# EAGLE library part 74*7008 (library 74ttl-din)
NOR/NAND/INVERTER
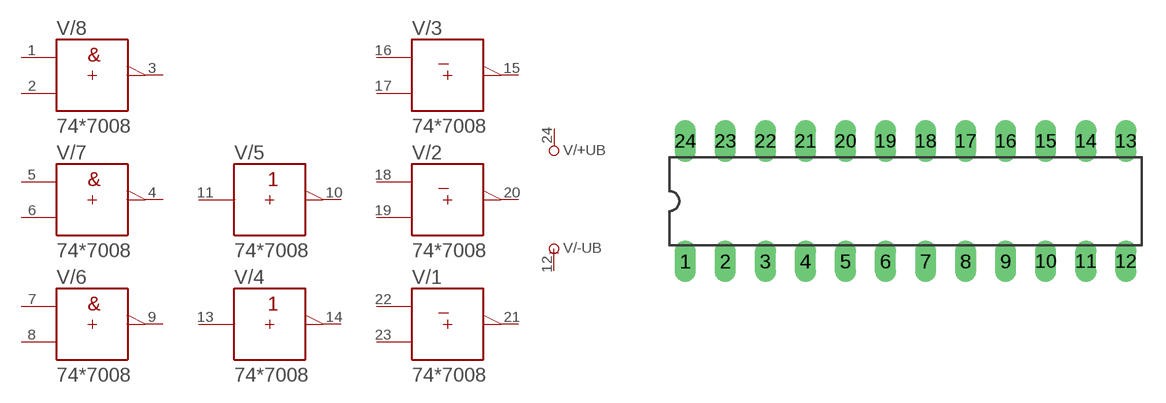
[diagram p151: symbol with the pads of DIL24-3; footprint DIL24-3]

Designator prefix V; gates /+UB=+UB /-UB=-UB /1=7008_8 /2=7008_7 /3=7008_6 /4=7008_5 /5=7008_4 /6=7008_3 /7=7008_2 /8=7008_1

## 747008N  [DIL24-3]
1  /8:A  in
2  /8:B  in
3  /8:Y  out
4  /7:Y  out
5  /7:A  in
6  /7:B  in
7  /6:A  in
8  /6:B  in
9  /6:Y  out
10  /5:Y  out
11  /5:A  in
12  /-UB:-UB  pwr
13  /4:A  in
14  /4:Y  out
15  /3:Y  out
16  /3:A  in
17  /3:B  in
18  /2:A  in
19  /2:B  in
20  /2:Y  out
21  /1:Y  out
22  /1:A  in
23  /1:B  in
24  /+UB:+UB  pwr

## Footprint DIL24-3 (pad centres in mm)
Dual In Line Package 0.3 inch
drill 0.813 long: 1 -13.97,-3.81; 2 -11.43,-3.81; 3 -8.89,-3.81; 4 -6.35,-3.81; 5 -3.81,-3.81; 6 -1.27,-3.81; 7 1.27,-3.81; 8 3.81,-3.81; 9 6.35,-3.81; 10 8.89,-3.81; 11 11.43,-3.81; 12 13.97,-3.81; 13 13.97,3.81; 14 11.43,3.81; 15 8.89,3.81; 16 6.35,3.81; 17 3.81,3.81; 18 1.27,3.81; 19 -1.27,3.81; 20 -3.81,3.81; 21 -6.35,3.81; 22 -8.89,3.81; 23 -11.43,3.81; 24 -13.97,3.81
